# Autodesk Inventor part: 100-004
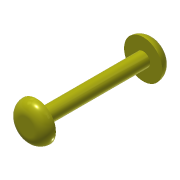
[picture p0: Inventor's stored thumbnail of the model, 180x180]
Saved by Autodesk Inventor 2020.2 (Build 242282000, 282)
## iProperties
Created: 2014-01
Part Number: 100-004
Material: Ogólny
Document SubType Name: Modeling
Designer: F.Stasiak
Density: 1 g/cm^3
Appearance: Żółta
Manager: www.cadconsulting.pl
Company: Fabian Stasiak CAD Consulting
Author: F.Stasiak
Subject: Zbiór ćwiczeń. Autodesk Inventor 2020. Kurs podstawowy
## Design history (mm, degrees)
sketch "Szkic1"
  geometry: C1 r 3.25 at (0, 0); 1 further point
  constraints: 1 centre point, 1 coincident
  dimensions: "d0" = 6.5 diameter of C1
extrude "Wyciągnięcie proste1" new body sketch "Szkic1" distance "d1" = 25; taper "d2" = 0 deg
sketch "Szkic2"
  geometry: C1 r 3.25 at (0, 0) reference; C2 r 9 at (0, 0)
  constraints: 1 centre point, 1 coincident
  dimensions: "d3" = 18 diameter of C2
extrude "Wyciągnięcie proste2" join sketch "Szkic2" distance "d4" = 5; taper "d5" = 0 deg
fillet "Zaokrąglenie1" dims "d6" = 5
mirror "Odbicie lustrzane1"
node "Bryła1"
